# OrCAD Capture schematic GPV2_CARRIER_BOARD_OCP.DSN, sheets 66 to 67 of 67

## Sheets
66 021 PCIE SWITCH (PWR3/VSS3): size C
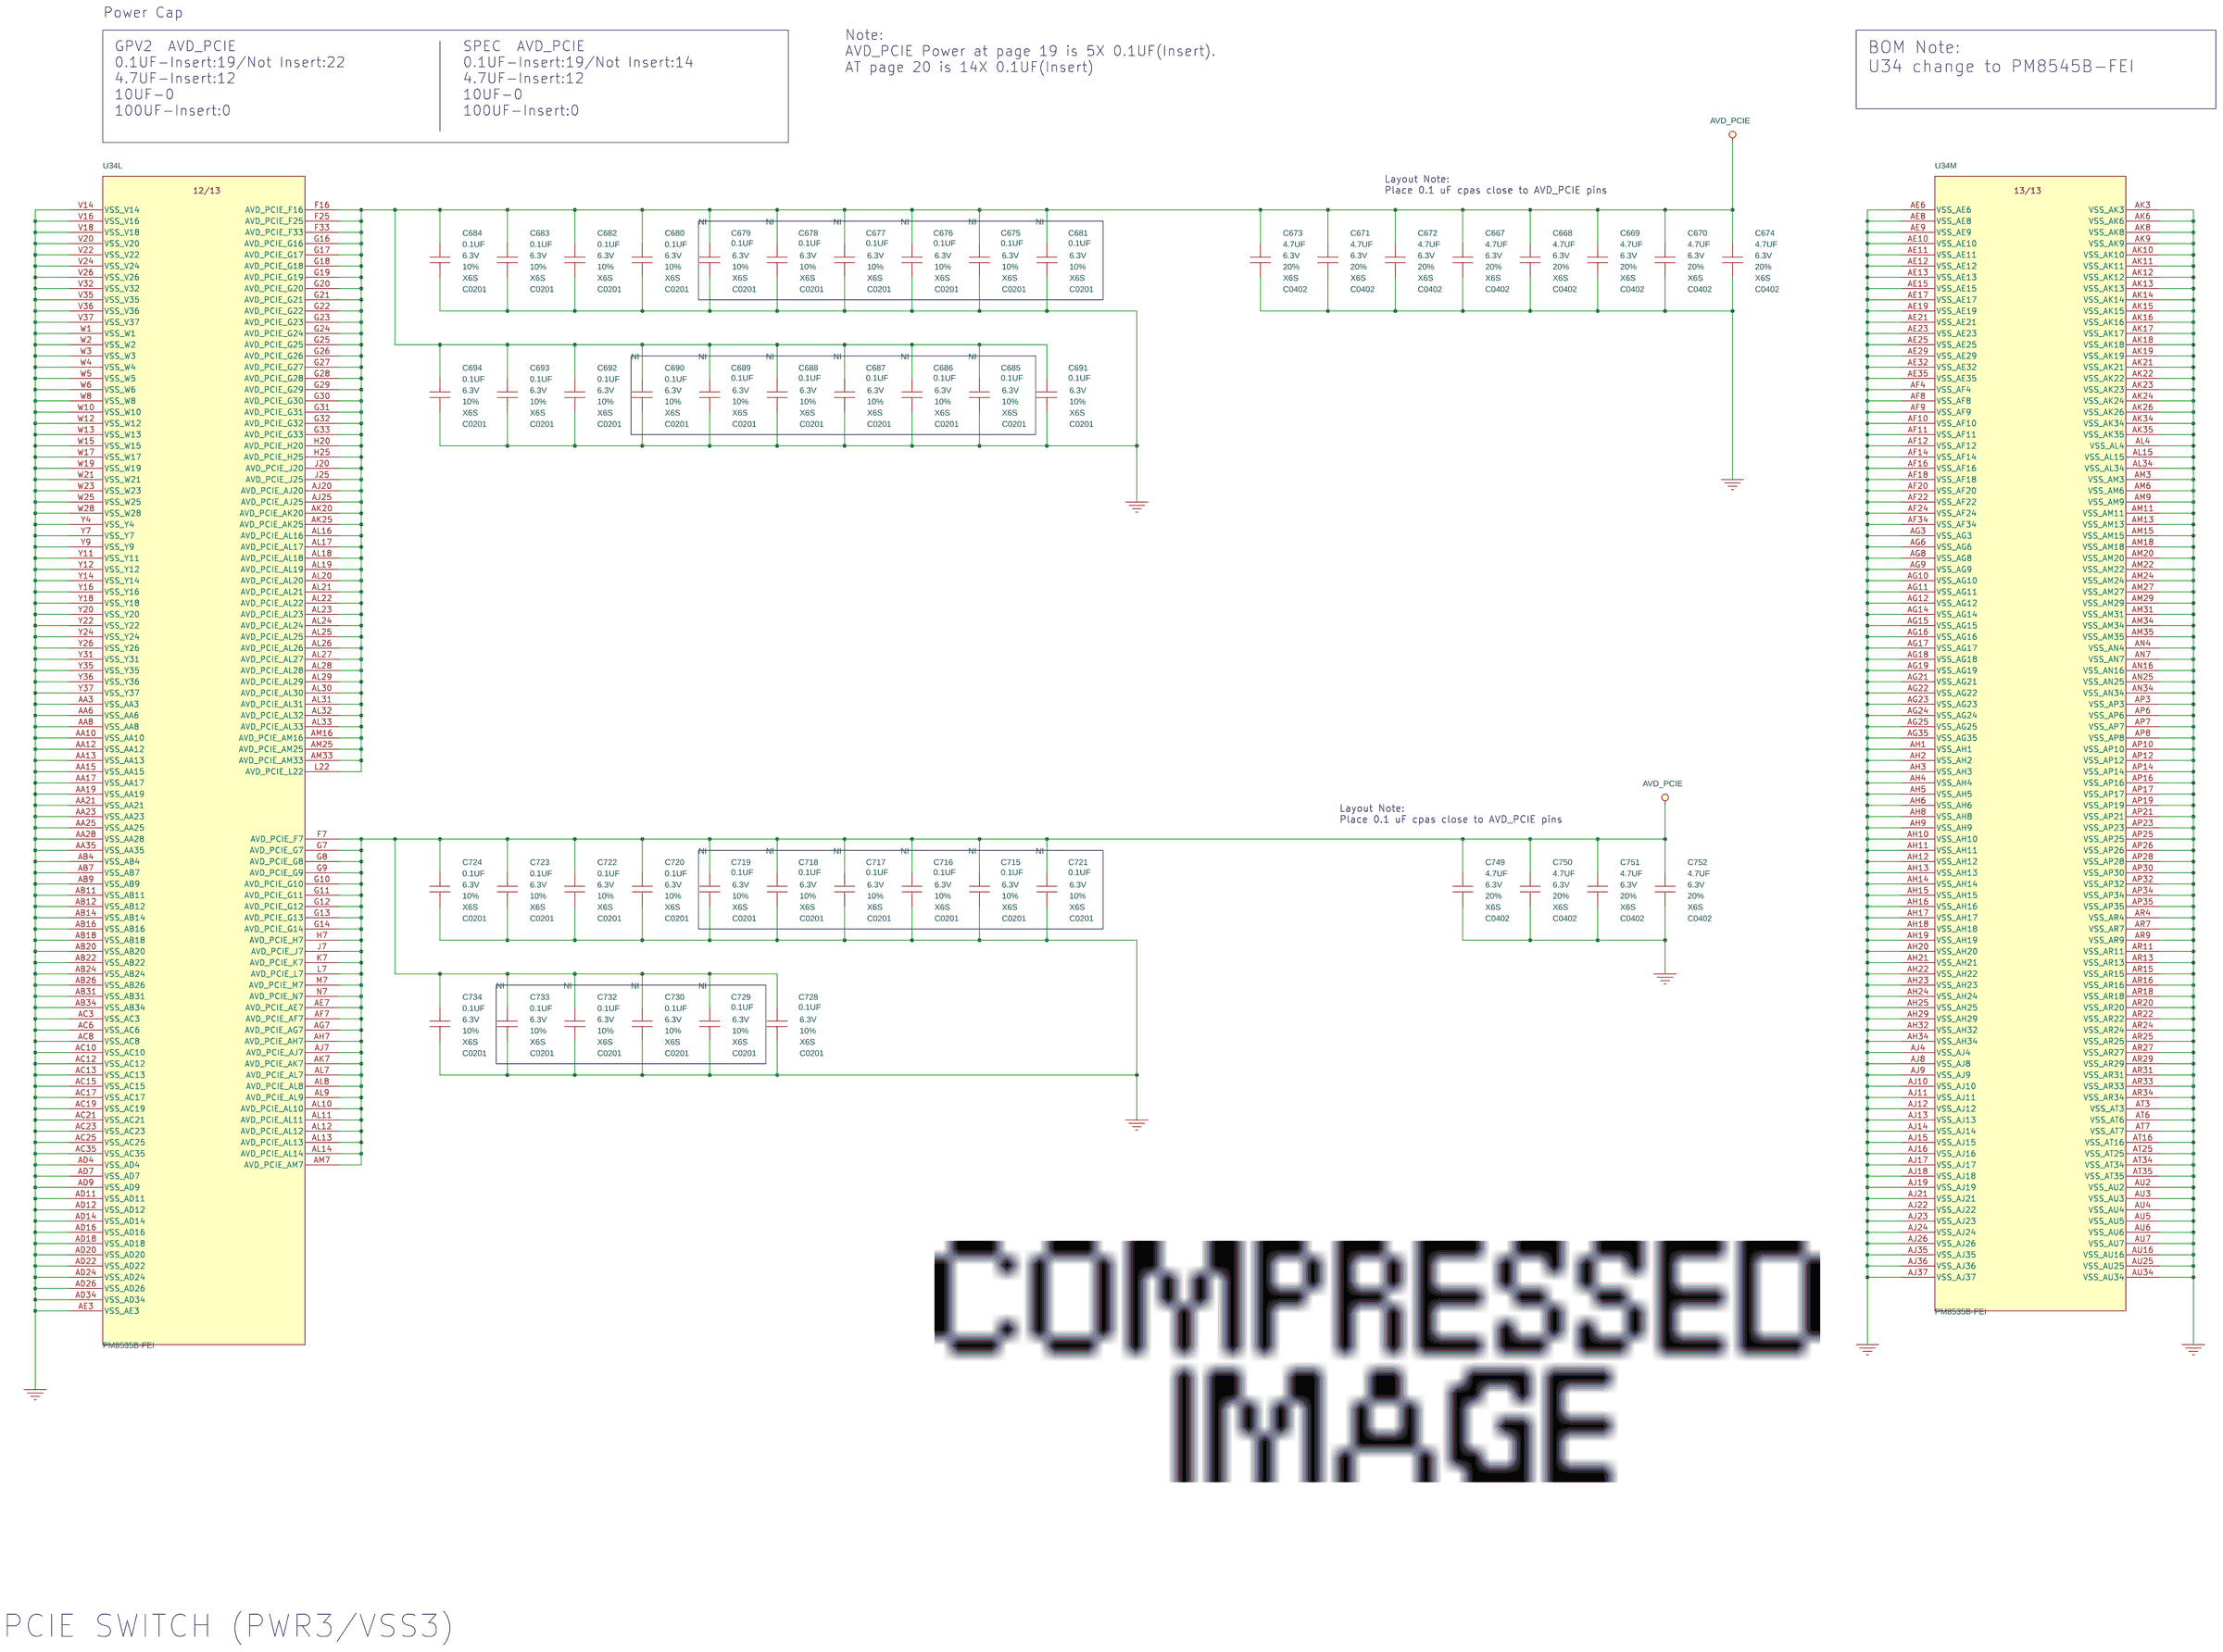
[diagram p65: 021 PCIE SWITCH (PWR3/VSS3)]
67 017 PCIE SWITCH (CLOCKS/RESET): size C
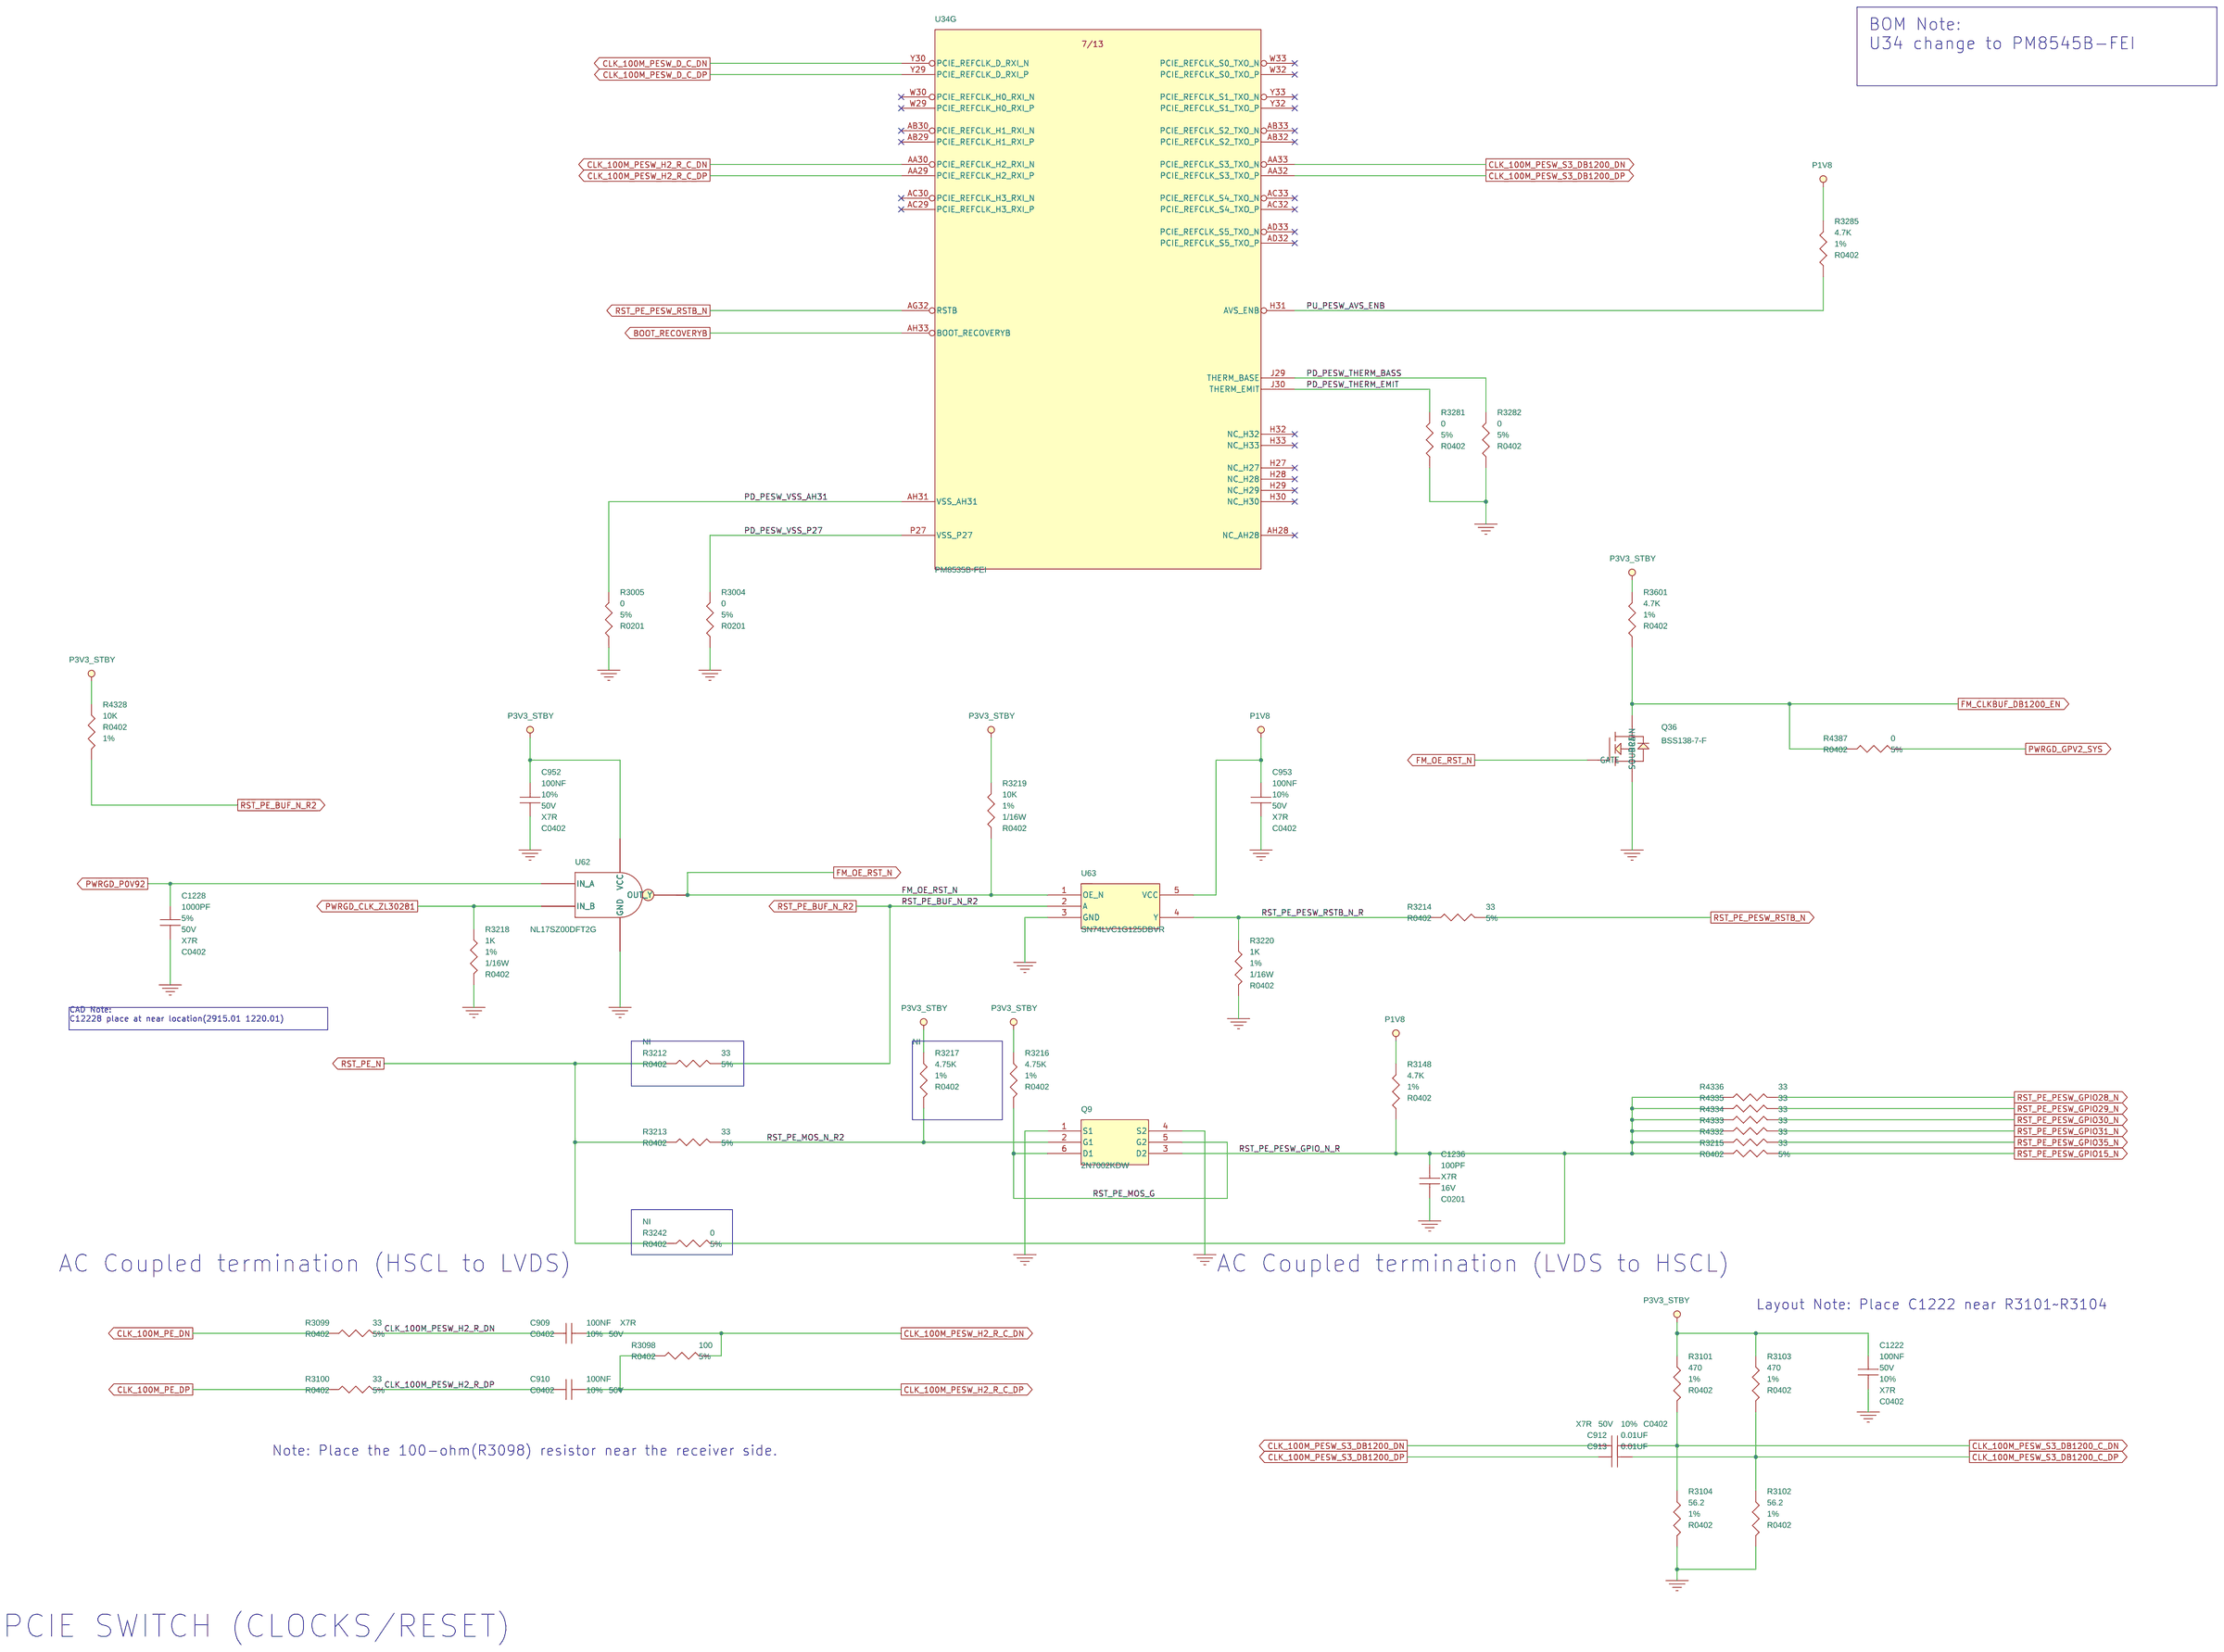
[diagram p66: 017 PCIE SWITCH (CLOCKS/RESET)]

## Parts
sheet 017 PCIE SWITCH (CLOCKS/RESET)
C909  100NF  [C0402]
C910  100NF  [C0402]
C912  0.01UF  [C0402]
C913  0.01UF  [C0402]
C952  100NF  [C0402]
C953  100NF  [C0402]
C1222  100NF  [C0402]
C1228  1000PF  [C0402]
C1236  100PF  [C0201]
Q9  2N7002KDW  [SOT363XD]
Q36  BSS138-7-F  [SOT23_GDSXC]
R3004  0  [R0201]
R3005  0  [R0201]
R3098  100  [R0402]
R3099  33  [R0402]
R3100  33  [R0402]
R3101  470  [R0402]
R3102  56.2  [R0402]
R3103  470  [R0402]
R3104  56.2  [R0402]
R3148  4.7K  [R0402]
R3212  33  [R0402]
R3213  33  [R0402]
R3214  33  [R0402]
R3215  33  [R0402]
R3216  4.75K  [R0402]
R3217  4.75K  [R0402]
R3218  1K  [R0402]
R3219  10K  [R0402]
R3220  1K  [R0402]
R3242  0  [R0402]
R3281  0  [R0402]
R3282  0  [R0402]
R3285  4.7K  [R0402]
R3601  4.7K  [R0402]
R4328  10K  [R0402]
R4332  33  [R0402]
R4333  33  [R0402]
R4334  33  [R0402]
R4335  33  [R0402]
R4336  33  [R0402]
R4387  0  [R0402]
U34  PM8535B-FEI  [BGA1311_1_37-5X37-5]  (sections A,B,C,D,E,F,G,H,I,J,K,L,M)
U62  NL17SZ00DFT2G  [SC70-5XA]
U63  SN74LVC1G125DBVR  [SOT23-5XE]
sheet 021 PCIE SWITCH (PWR3/VSS3)
C667  4.7UF  [C0402]
C668  4.7UF  [C0402]
C669  4.7UF  [C0402]
C670  4.7UF  [C0402]
C671  4.7UF  [C0402]
C672  4.7UF  [C0402]
C673  4.7UF  [C0402]
C674  4.7UF  [C0402]
C675  0.1UF  [C0201]
C676  0.1UF  [C0201]
C677  0.1UF  [C0201]
C678  0.1UF  [C0201]
C679  0.1UF  [C0201]
C680  0.1UF  [C0201]
C681  0.1UF  [C0201]
C682  0.1UF  [C0201]
C683  0.1UF  [C0201]
C684  0.1UF  [C0201]
C685  0.1UF  [C0201]
C686  0.1UF  [C0201]
C687  0.1UF  [C0201]
C688  0.1UF  [C0201]
C689  0.1UF  [C0201]
C690  0.1UF  [C0201]
C691  0.1UF  [C0201]
C692  0.1UF  [C0201]
C693  0.1UF  [C0201]
C694  0.1UF  [C0201]
C715  0.1UF  [C0201]
C716  0.1UF  [C0201]
C717  0.1UF  [C0201]
C718  0.1UF  [C0201]
C719  0.1UF  [C0201]
C720  0.1UF  [C0201]
C721  0.1UF  [C0201]
C722  0.1UF  [C0201]
C723  0.1UF  [C0201]
C724  0.1UF  [C0201]
C728  0.1UF  [C0201]
C729  0.1UF  [C0201]
C730  0.1UF  [C0201]
C732  0.1UF  [C0201]
C733  0.1UF  [C0201]
C734  0.1UF  [C0201]
C749  4.7UF  [C0402]
C750  4.7UF  [C0402]
C751  4.7UF  [C0402]
C752  4.7UF  [C0402]

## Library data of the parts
C909 C910 C952 C953 C1222 = CAP_NP: CAP CHIP 100NF 50V(+-10%,X7R,0402); CLASS: DISCRETE; MATERIAL: X7R; Manuf_PN: CC0402KRX7R9BB104; Manuf_name: YAGEO CORPORATION; Manuftr: YGO; Part_Type: *LF_C0402; TOLERANCE: 10%; VOLTAGE: 50V
C912 C913 = CAP_NP: CAP CHIP 0.01U 50V(+-10%,X7R,0402); CLASS: DISCRETE; MATERIAL: X7R; Manuf_PN: WBM155R71H103K; Manuf_name: MURATA ERIE N.A. INC TAIWAN BRANCH Okayama Murata Mfg.Co.,Ltd.; Manuftr: MUR; Part_Type: *LF_C0402; TOLERANCE: 10%; VOLTAGE: 50V
C1228 = CAP_NP: CAP CHIP 1000P 50V(+-5%.X7R.0402); CLASS: DISCRETE; MATERIAL: X7R; Manuf_PN: C1005X7R102JGT; Manuf_name: ACER PERIPHERALS INC.(Darfon Electronics Corp.); Manuftr: API; Part_Type: *LF_C0402; TOLERANCE: 5%; VOLTAGE: 50V
C1236 = CAP_NP: CAP CHIP 100PF 16V(+-10%,X7R,0201); CLASS: DISCRETE; MATERIAL: X7R; Manuf_PN: GRM033R71C101K; Manuf_name: MURATA ERIE N.A. INC TAIWAN BRANCH Okayama Murata Mfg.Co.,Ltd.Wakura Murata Mfg.; Manuftr: MUR; Part_Type: *LF_C0201; TOLERANCE: 10%; VOLTAGE: 16V
Q9 = MOSFET_DUAL_6P: TRANS MOS 2N7002KDW(60V115MA,0.2W)SOT363; CLASS: IC; MATERIAL: IC; Manuf_name: PAN JIT INTERNATIONAL INC.; Manuftr: PJT; Part_Type: *LF_Semiconductor
Q36 = MOSFET_N_0: TRANS MOSFET BSS138-7-F(50V,0.2A); CLASS: IC; MATERIAL: IC; Manuf_name: DIODES TAIWAN CO.,LTD.; Manuftr: DDS; Part_Type: *LF_Semiconductor
R3004 R3005 = R: RES CHIP 0(1/20W,+-5%,0201); CLASS: DISCRETE; MATERIAL: CHIP; Manuf_PN: RC0201JR-130RL; Manuf_name: YAGEO CORPORATION; Manuftr: YGO; Part_Type: *LF_Resistor; TOLERANCE: 5%; WATTAGE: 1/20W
R3098 = R: RES CHIP 100 1/16W +-5% (0402); CLASS: DISCRETE; MATERIAL: CHIP; Manuf_PN: RR0510S-101-JN; Manuf_name: CYNTEC CO.. LTD.; Manuftr: CYN; Part_Type: *LF_Resistor; TOLERANCE: 5%; WATTAGE: 1/16W
R3099 R3100 = R: RES CHIP 33 1/16W +-5% (0402); BOM: AST2300; CLASS: DISCRETE; MATERIAL: CHIP; Manuf_PN: RR0510S-330-JN; Manuf_name: CYNTEC CO.. LTD.; Manufacturer: CYN; Manuftr: CYN; Part_Type: *LF_Resistor; TOLERANCE: 5%; WATTAGE: 1/16W
R3101 R3103 = R: RES CHIP 470 1/16W +-1%(0402); CLASS: DISCRETE; MATERIAL: CHIP; Manuf_PN: RR0510S-471-FN; Manuf_name: CYNTEC CO.. LTD.; Manuftr: CYN; Part_Type: *LF_Resistor; TOLERANCE: 1%; WATTAGE: 1/16W
R3102 R3104 = R: RES CHIP 56.2 1/16W +-1% (0402); CLASS: DISCRETE; FPLIST: R0402,R0402-0201; MATERIAL: CHIP; Manuf_PN: CR0256R2F002; Manuf_name: "RTECH TECHNOLOGY CO..LTD.(Compostar)"; Manuftr: RHT; Part_Type: Resistor; TOLERANCE: 1%; WATTAGE: 1/16W
R3148 R3285 R3601 = R: RES CHIP 4.7K 1/16W +-1%(0402); CLASS: DISCRETE; MATERIAL: CHIP; Manuf_PN: RTT024701FTH; Manuf_name: RALEC ELECTRONIC CO.; Manuftr: RLC; Part_Type: *LF_Resistor; TOLERANCE: 1%; WATTAGE: 1/16W
R3212 = R: RES CHIP 33 1/16W +-5% (0402); CLASS: DISCRETE; MATERIAL: CHIP; Manuf_PN: RR0510S-330-JN; Manuf_name: CYNTEC CO.. LTD.; Manuftr: CYN; Not_insert: NI; Part_Type: *LF_Resistor; TOLERANCE: 5%; WATTAGE: 1/16W
R3213-R3215 R4332-R4336 = R: RES CHIP 33 1/16W +-5% (0402); CLASS: DISCRETE; MATERIAL: CHIP; Manuf_PN: RR0510S-330-JN; Manuf_name: CYNTEC CO.. LTD.; Manuftr: CYN; Part_Type: *LF_Resistor; TOLERANCE: 5%; WATTAGE: 1/16W
R3216 = R: RES CHIP 4.75K 1/16W +-1%(0402); CLASS: DISCRETE; MATERIAL: CHIP; Manuf_PN: RR0510S-4751-FN; Manuf_name: CYNTEC CO.. LTD.; Manuftr: CYN; Part_Type: *LF_Resistor; TOLERANCE: 1%; WATTAGE: 1/16W
R3217 = R: RES CHIP 4.75K 1/16W +-1%(0402); CLASS: DISCRETE; MATERIAL: CHIP; Manuf_PN: RR0510S-4751-FN; Manuf_name: CYNTEC CO.. LTD.; Manuftr: CYN; Not_insert: NI; Part_Type: *LF_Resistor; TOLERANCE: 1%; WATTAGE: 1/16W
R3218 R3220 = R: RES CHIP 1K 1/16W +-1% (0402); CLASS: DISCRETE; MATERIAL: CHIP; Manuf_PN: RR0510S-102-FN; Manuf_name: CYNTEC CO.. LTD.; Manuftr: CYN; Part_Type: *LF_Resistor; TOLERANCE: 1%; WATTAGE: 1/16W
R3219 = R: RES CHIP 10K 1/16W +-1% (0402); CLASS: DISCRETE; MATERIAL: CHIP; Manuf_PN: RR0510S-103-FN; Manuf_name: CYNTEC CO.. LTD.; Manufacturer: CYN; Manuftr: CYN; Part_Type: *LF_Resistor; TOLERANCE: 1%; WATTAGE: 1/16W
R3242 = R: RESISTOR CHIP 0 1/16W +-5%(0402); BOM: AST2300; CLASS: DISCRETE; MATERIAL: CHIP; Manuf_PN: RR0510X-000-XN; Manuf_name: CYNTEC CO.. LTD.; Manufacturer: CYN; Manuftr: CYN; Not_insert: NI; Part_Type: *LF_Resistor; TOLERANCE: 5%; WATTAGE: 1/16W
R3281 R3282 R4387 = R: RESISTOR CHIP 0 1/16W +-5%(0402); BOM: AST2300; CLASS: DISCRETE; MATERIAL: CHIP; Manuf_PN: RR0510X-000-XN; Manuf_name: CYNTEC CO.. LTD.; Manufacturer: CYN; Manuftr: CYN; Part_Type: *LF_Resistor; TOLERANCE: 5%; WATTAGE: 1/16W
R4328 = R: RES CHIP 10K 1/16W +-1% (0402); CLASS: DISCRETE; FPLIST: R0402,R0402-0201; MATERIAL: CHIP; Manuf_PN: RR0510S-103-FN; Manuf_name: CYNTEC CO.. LTD.; Manufacturer: CYN; Manuftr: CYN; Part_Type: *LF_Resistor; TOLERANCE: 1%; WATTAGE: 1/16W
U34 = PM8535BFEI: IC CTRL(1311P)PM8535B-FEI(FCBGA); CLASS: IC; ESD_CDM: N/A; ESD_HBM: N/A; ESD_MM: N/A; MATERIAL: IC; MSD: NA; Manuf_name: Microsemi Corporation ( Microsemi Taiwan); Manuftr: MST; PIN_LENGTH_LONG_PIN: 0 MILS; PIN_LENGTH_SHORT_PIN: 0 MILS; Part_Type: *LF_Chipset
U62 = NL17SZ00DFT2G: IC OTHER(5P) NL17SZ00DFT2G(SOT-353); CLASS: IC; ESD_CDM: N/A; ESD_HBM: 2000; ESD_MM: 200; MATERIAL: IC; MSD: Level-1; Manuf_name: ON SEMICONDUCTOR; Manuftr: ONS; PIN_LENGTH_LONG_PIN: 0 MILS; PIN_LENGTH_SHORT_PIN: 0 MILS; Part_Type: *LF_Chipset
U63 = SN74LVC1G125DBVR: IC(5P)SN74LVC1G125DBVR(SOT-23); CLASS: IC; MATERIAL: IC; Manuf_name: TEXAS INSTRUMENTS SUPPLY CO.,; Manuftr: TIC; Part_Type: *LF_Chipset
C667-C674 C749-C752 = CAP_NP: CAP CHIP 4.7UF 6.3V(+-20%,X6S,0402); CLASS: DISCRETE; MATERIAL: X6S; Manuf_PN: GRM155C80J475M; Manuf_name: MURATA ERIE N.A. INC TAIWAN BRANCH Okayama Murata Mfg.Co.,; Manuftr: MUR; Part_Type: *LF_C0402; TOLERANCE: 20%; VOLTAGE: 6.3V
C675-C679 C681 C685-C690 C715-C719 C721 C729 C730 C732 C733 = CAP_NP: CAP CHIP 0.1UF 6.3V(10%,X6S,0201,H0.3); CLASS: DISCRETE; MATERIAL: X6S; Manuf_PN: GRM033C80J104K; Manuf_name: MURATA ERIE N.A. INC TAIWAN BRANCH Okayama Murata Mfg.Co.,Ltd.Wakura Murata Mfg.; Manuftr: MUR; Not_insert: NI; Part_Type: *LF_C0201; TOLERANCE: 10%; VOLTAGE: 6.3V
C680 C682-C684 C691-C694 C720 C722-C724 C728 C734 = CAP_NP: CAP CHIP 0.1UF 6.3V(10%,X6S,0201,H0.3); CLASS: DISCRETE; MATERIAL: X6S; Manuf_PN: GRM033C80J104K; Manuf_name: MURATA ERIE N.A. INC TAIWAN BRANCH Okayama Murata Mfg.Co.,Ltd.Wakura Murata Mfg.; Manuftr: MUR; Part_Type: *LF_C0201; TOLERANCE: 10%; VOLTAGE: 6.3V

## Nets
GND: C667.2 C668.2 C669.2 C670.2 C671.2 C672.2 C673.2 C674.2 C675.2 C676.2 C677.2 C678.2 C679.2 C680.2 C681.2 C682.2 C683.2 C684.2 C685.2 C686.2 C687.2 C688.2 C689.2 C690.2 C691.2 C692.2 C693.2 C694.2 C715.2 C716.2 C717.2 C718.2 C719.2 C720.2 C721.2 C722.2 C723.2 C724.2 C728.2 C729.2 C730.2 C732.2 C733.2 C734.2 C749.2 C750.2 C751.2 C752.2 C952.1 C953.1 C1222.2 C1228.2 C1236.2 Q9.1(S1) Q9.4(S2) Q36.S(SOURCE) R3004.1 R3005.1 R3102.2 R3104.2 R3218.2 R3220.2 R3281.1 R3282.1 U34.AA3(VSS) U34.AA6(VSS) U34.AA8(VSS) U34.AA10(VSS) U34.AA12(VSS) U34.AA13(VSS) U34.AA15(VSS) U34.AA17(VSS) U34.AA19(VSS) U34.AA21(VSS) U34.AA23(VSS) U34.AA25(VSS) U34.AA28(VSS) U34.AA35(VSS) U34.AB4(VSS) U34.AB7(VSS) U34.AB9(VSS) U34.AB11(VSS) U34.AB12(VSS) U34.AB14(VSS) U34.AB16(VSS) U34.AB18(VSS) U34.AB20(VSS) U34.AB22(VSS) U34.AB24(VSS) U34.AB26(VSS) U34.AB31(VSS) U34.AB34(VSS) U34.AC3(VSS) U34.AC6(VSS) U34.AC8(VSS) U34.AC10(VSS) U34.AC12(VSS) U34.AC13(VSS) U34.AC15(VSS) U34.AC17(VSS) U34.AC19(VSS) U34.AC21(VSS) U34.AC23(VSS) U34.AC25(VSS) U34.AC35(VSS) U34.AD4(VSS) U34.AD7(VSS) U34.AD9(VSS) U34.AD11(VSS) U34.AD12(VSS) U34.AD14(VSS) U34.AD16(VSS) U34.AD18(VSS) U34.AD20(VSS) U34.AD22(VSS) U34.AD24(VSS) U34.AD26(VSS) U34.AD34(VSS) U34.AE3(VSS) U34.AE6(VSS) U34.AE8(VSS) U34.AE9(VSS) U34.AE10(VSS) U34.AE11(VSS) U34.AE12(VSS) U34.AE13(VSS) U34.AE15(VSS) U34.AE17(VSS) U34.AE19(VSS) U34.AE21(VSS) U34.AE23(VSS) U34.AE25(VSS) U34.AE29(VSS) U34.AE32(VSS) U34.AE35(VSS) U34.AF4(VSS) U34.AF8(VSS) U34.AF9(VSS) U34.AF10(VSS) U34.AF11(VSS) U34.AF12(VSS) U34.AF14(VSS) U34.AF16(VSS) U34.AF18(VSS) U34.AF20(VSS) U34.AF22(VSS) U34.AF24(VSS) U34.AF34(VSS) U34.AG3(VSS) U34.AG6(VSS) U34.AG8(VSS) U34.AG9(VSS) U34.AG10(VSS) U34.AG11(VSS) U34.AG12(VSS) U34.AG14(VSS) U34.AG15(VSS) U34.AG16(VSS) U34.AG17(VSS) U34.AG18(VSS) U34.AG19(VSS) U34.AG21(VSS) U34.AG22(VSS) U34.AG23(VSS) U34.AG24(VSS) U34.AG25(VSS) U34.AG35(VSS) U34.AH1(VSS) U34.AH2(VSS) U34.AH3(VSS) U34.AH4(VSS) U34.AH5(VSS) U34.AH6(VSS) U34.AH8(VSS) U34.AH9(VSS) U34.AH10(VSS) U34.AH11(VSS) U34.AH12(VSS) U34.AH13(VSS) U34.AH14(VSS) U34.AH15(VSS) U34.AH16(VSS) U34.AH17(VSS) U34.AH18(VSS) U34.AH19(VSS) U34.AH20(VSS) U34.AH21(VSS) U34.AH22(VSS) U34.AH23(VSS) U34.AH24(VSS) U34.AH25(VSS) U34.AH29(VSS) U34.AH32(VSS) U34.AH34(VSS) U34.AJ4(VSS) U34.AJ8(VSS) U34.AJ9(VSS) U34.AJ10(VSS) U34.AJ11(VSS) U34.AJ12(VSS) U34.AJ13(VSS) U34.AJ14(VSS) U34.AJ15(VSS) U34.AJ16(VSS) U34.AJ17(VSS) U34.AJ18(VSS) U34.AJ19(VSS) U34.AJ21(VSS) U34.AJ22(VSS) U34.AJ23(VSS) U34.AJ24(VSS) U34.AJ26(VSS) U34.AJ35(VSS) U34.AJ36(VSS) U34.AJ37(VSS) U34.AK3(VSS) U34.AK6(VSS) U34.AK8(VSS) U34.AK9(VSS) U34.AK10(VSS) U34.AK11(VSS) U34.AK12(VSS) U34.AK13(VSS) U34.AK14(VSS) U34.AK15(VSS) U34.AK16(VSS) U34.AK17(VSS) U34.AK18(VSS) U34.AK19(VSS) U34.AK21(VSS) U34.AK22(VSS) U34.AK23(VSS) U34.AK24(VSS) U34.AK26(VSS) U34.AK34(VSS) U34.AK35(VSS) U34.AL4(VSS) U34.AL15(VSS) U34.AL34(VSS) U34.AM3(VSS) U34.AM6(VSS) U34.AM9(VSS) U34.AM11(VSS) U34.AM13(VSS) U34.AM15(VSS) U34.AM18(VSS) U34.AM20(VSS) U34.AM22(VSS) U34.AM24(VSS) U34.AM27(VSS) U34.AM29(VSS) U34.AM31(VSS) U34.AM34(VSS) U34.AM35(VSS) U34.AN4(VSS) U34.AN7(VSS) U34.AN16(VSS) U34.AN25(VSS) U34.AN34(VSS) U34.AP3(VSS) U34.AP6(VSS) U34.AP7(VSS) U34.AP8(VSS) U34.AP10(VSS) U34.AP12(VSS) U34.AP14(VSS) U34.AP16(VSS) U34.AP17(VSS) U34.AP19(VSS) U34.AP21(VSS) U34.AP23(VSS) U34.AP25(VSS) U34.AP26(VSS) U34.AP28(VSS) U34.AP30(VSS) U34.AP32(VSS) U34.AP34(VSS) U34.AP35(VSS) U34.AR4(VSS) U34.AR7(VSS) U34.AR9(VSS) U34.AR11(VSS) U34.AR13(VSS) U34.AR15(VSS) U34.AR16(VSS) U34.AR18(VSS) U34.AR20(VSS) U34.AR22(VSS) U34.AR24(VSS) U34.AR25(VSS) U34.AR27(VSS) U34.AR29(VSS) U34.AR31(VSS) U34.AR33(VSS) U34.AR34(VSS) U34.AT3(VSS) U34.AT6(VSS) U34.AT7(VSS) U34.AT16(VSS) U34.AT25(VSS) U34.AT34(VSS) U34.AT35(VSS) U34.AU2(VSS) U34.AU3(VSS) U34.AU4(VSS) U34.AU5(VSS) U34.AU6(VSS) U34.AU7(VSS) U34.AU16(VSS) U34.AU25(VSS) U34.AU34(VSS) U34.V14(VSS) U34.V16(VSS) U34.V18(VSS) U34.V20(VSS) U34.V22(VSS) U34.V24(VSS) U34.V26(VSS) U34.V32(VSS) U34.V35(VSS) U34.V36(VSS) U34.V37(VSS) U34.W1(VSS) U34.W2(VSS) U34.W3(VSS) U34.W4(VSS) U34.W5(VSS) U34.W6(VSS) U34.W8(VSS) U34.W10(VSS) U34.W12(VSS) U34.W13(VSS) U34.W15(VSS) U34.W17(VSS) U34.W19(VSS) U34.W21(VSS) U34.W23(VSS) U34.W25(VSS) U34.W28(VSS) U34.Y4(VSS) U34.Y7(VSS) U34.Y9(VSS) U34.Y11(VSS) U34.Y12(VSS) U34.Y14(VSS) U34.Y16(VSS) U34.Y18(VSS) U34.Y20(VSS) U34.Y22(VSS) U34.Y24(VSS) U34.Y26(VSS) U34.Y31(VSS) U34.Y35(VSS) U34.Y36(VSS) U34.Y37(VSS) U62.3(GND) U63.3(GND) ; also on sheet 12 13 17 18 19 20 21 22 23 24 25 26 27 28 29 30 31 32 33 34 35 36 37 38 39 40 41 42 43 44 45 46 47 48 49 50 52 53 54 55 56 57 58 61 62 63 64 65
P1V8: C953.2 R3148.2 R3285.2 U63.5(VCC) ; also on sheet 17 18 19 22 23 24 25 26 27 28 29 30 31 32 33 34 35 36 37 44 49 50 53 58 62 65
P3V3_STBY: C952.2 C1222.1 R3101.1 R3103.1 R3216.1 R3217.1 R3219.1 R3601.2 R4328.1 U62.5(VCC) ; also on sheet 12 17 18 19 20 22 23 24 25 26 27 28 29 30 31 32 33 34 35 36 37 38 39 40 41 42 43 44 45 46 47 48 49 50 52 53 54 55 56 57 58 61
AVD_PCIE: C667.1 C668.1 C669.1 C670.1 C671.1 C672.1 C673.1 C674.1 C675.1 C676.1 C677.1 C678.1 C679.1 C680.1 C681.1 C682.1 C683.1 C684.1 C685.1 C686.1 C687.1 C688.1 C689.1 C690.1 C691.1 C692.1 C693.1 C694.1 C715.1 C716.1 C717.1 C718.1 C719.1 C720.1 C721.1 C722.1 C723.1 C724.1 C728.1 C729.1 C730.1 C732.1 C733.1 C734.1 C749.1 C750.1 C751.1 C752.1 U34.AE7(AVD_PCIE) U34.AF7(AVD_PCIE) U34.AG7(AVD_PCIE) U34.AH7(AVD_PCIE) U34.AJ7(AVD_PCIE) U34.AJ20(AVD_PCIE) U34.AJ25(AVD_PCIE) U34.AK7(AVD_PCIE) U34.AK20(AVD_PCIE) U34.AK25(AVD_PCIE) U34.AL7(AVD_PCIE) U34.AL8(AVD_PCIE) U34.AL9(AVD_PCIE) U34.AL10(AVD_PCIE) U34.AL11(AVD_PCIE) U34.AL12(AVD_PCIE) U34.AL13(AVD_PCIE) U34.AL14(AVD_PCIE) U34.AL16(AVD_PCIE) U34.AL17(AVD_PCIE) U34.AL18(AVD_PCIE) U34.AL19(AVD_PCIE) U34.AL20(AVD_PCIE) U34.AL21(AVD_PCIE) U34.AL22(AVD_PCIE) U34.AL23(AVD_PCIE) U34.AL24(AVD_PCIE) U34.AL25(AVD_PCIE) U34.AL26(AVD_PCIE) U34.AL27(AVD_PCIE) U34.AL28(AVD_PCIE) U34.AL29(AVD_PCIE) U34.AL30(AVD_PCIE) U34.AL31(AVD_PCIE) U34.AL32(AVD_PCIE) U34.AL33(AVD_PCIE) U34.AM7(AVD_PCIE) U34.AM16(AVD_PCIE) U34.AM25(AVD_PCIE) U34.AM33(AVD_PCIE) U34.F7(AVD_PCIE) U34.F16(AVD_PCIE) U34.F25(AVD_PCIE) U34.F33(AVD_PCIE) U34.G7(AVD_PCIE) U34.G8(AVD_PCIE) U34.G9(AVD_PCIE) U34.G10(AVD_PCIE) U34.G11(AVD_PCIE) U34.G12(AVD_PCIE) U34.G13(AVD_PCIE) U34.G14(AVD_PCIE) U34.G16(AVD_PCIE) U34.G17(AVD_PCIE) U34.G18(AVD_PCIE) U34.G19(AVD_PCIE) U34.G20(AVD_PCIE) U34.G21(AVD_PCIE) U34.G22(AVD_PCIE) U34.G23(AVD_PCIE) U34.G24(AVD_PCIE) U34.G25(AVD_PCIE) U34.G26(AVD_PCIE) U34.G27(AVD_PCIE) U34.G28(AVD_PCIE) U34.G29(AVD_PCIE) U34.G30(AVD_PCIE) U34.G31(AVD_PCIE) U34.G32(AVD_PCIE) U34.G33(AVD_PCIE) U34.H7(AVD_PCIE) U34.H20(AVD_PCIE) U34.H25(AVD_PCIE) U34.J7(AVD_PCIE) U34.J20(AVD_PCIE) U34.J25(AVD_PCIE) U34.K7(AVD_PCIE) U34.L7(AVD_PCIE) U34.L22(AVD_PCIE) U34.M7(AVD_PCIE) U34.N7(AVD_PCIE) ; also on sheet 64
BOOT_RECOVERYB: U34.AH33(BOOT_RECOVERYB) ; also on sheet 17
CLK_100M_PE_DN: R3099.1 ; also on sheet 12
CLK_100M_PE_DP: R3100.1 ; also on sheet 12
CLK_100M_PESW_D_C_DN: U34.Y30(PCIE_REFCLK_D_RXI_N) ; also on sheet 19
CLK_100M_PESW_D_C_DP: U34.Y29(PCIE_REFCLK_D_RXI_P) ; also on sheet 19
CLK_100M_PESW_H2_R_C_DN: C909.2 R3098.2 U34.AA30(PCIE_REFCLK_H2_RXI_N)
CLK_100M_PESW_H2_R_C_DP: C910.2 R3098.1 U34.AA29(PCIE_REFCLK_H2_RXI_P)
CLK_100M_PESW_H2_R_DN: C909.1 R3099.2
CLK_100M_PESW_H2_R_DP: C910.1 R3100.2
CLK_100M_PESW_S3_DB1200_C_DN: C912.2 R3101.2 R3104.1 ; also on sheet 20
CLK_100M_PESW_S3_DB1200_C_DP: C913.2 R3102.1 R3103.2 ; also on sheet 20
CLK_100M_PESW_S3_DB1200_DN: C912.1 U34.AA33(PCIE_REFCLK_S3_TXO_N)
CLK_100M_PESW_S3_DB1200_DP: C913.1 U34.AA32(PCIE_REFCLK_S3_TXO_P)
FM_CLKBUF_DB1200_EN: Q36.D(DRAIN) R3601.1 R4387.1 ; also on sheet 20
FM_OE_RST_N: Q36.G(GATE) R3219.2 U62.4(OUT_Y) U63.1(OE_N)
PD_PESW_THERM_BASS: R3282.2 U34.J29(THERM_BASE)
PD_PESW_THERM_EMIT: R3281.2 U34.J30(THERM_EMIT)
PD_PESW_VSS_AH31: R3005.2 U34.AH31(VSS)
PD_PESW_VSS_P27: R3004.2 U34.P27(VSS)
PU_PESW_AVS_ENB: R3285.1 U34.H31(AVS_ENB)
PWRGD_CLK_ZL30281: R3218.1 U62.2(IN_B) ; also on sheet 19
PWRGD_GPV2_SYS: R4387.2 ; also on sheet 47
PWRGD_P0V92: C1228.1 U62.1(IN_A) ; also on sheet 57
RST_PE_BUF_N_R2: R3212.2 R4328.2 U63.2(A)
RST_PE_MOS_G: Q9.5(G2) Q9.6(D1) R3216.2
RST_PE_MOS_N_R2: Q9.2(G1) R3213.2 R3217.2
RST_PE_N: R3212.1 R3213.1 R3242.1 ; also on sheet 12 46
RST_PE_PESW_GPIO15_N: R3215.2 ; also on sheet 17
RST_PE_PESW_GPIO28_N: R4336.2 ; also on sheet 17
RST_PE_PESW_GPIO29_N: R4335.2 ; also on sheet 17
RST_PE_PESW_GPIO30_N: R4334.2 ; also on sheet 17
RST_PE_PESW_GPIO31_N: R4333.2 ; also on sheet 17
RST_PE_PESW_GPIO35_N: R4332.2 ; also on sheet 17
RST_PE_PESW_GPIO_N_R: C1236.1 Q9.3(D2) R3148.1 R3215.1 R3242.2 R4332.1 R4333.1 R4334.1 R4335.1 R4336.1
RST_PE_PESW_RSTB_N: R3214.2 U34.AG32(RSTB)
RST_PE_PESW_RSTB_N_R: R3214.1 R3220.1 U63.4(Y)

Not connected (* = marked no-connect by the designer): U34 AB29(PCIE_REFCLK_H1_RXI_P)* AB30(PCIE_REFCLK_H1_RXI_N)* AB32(PCIE_REFCLK_S2_TXO_P)* AB33(PCIE_REFCLK_S2_TXO_N)* AC29(PCIE_REFCLK_H3_RXI_P)* AC30(PCIE_REFCLK_H3_RXI_N)* AC32(PCIE_REFCLK_S4_TXO_P)* AC33(PCIE_REFCLK_S4_TXO_N)* AD32(PCIE_REFCLK_S5_TXO_P)* AD33(PCIE_REFCLK_S5_TXO_N)* AH28(NC)* H27(NC)* H28(NC)* H29(NC)* H30(NC)* H32(NC)* H33(NC)* W29(PCIE_REFCLK_H0_RXI_P)* W30(PCIE_REFCLK_H0_RXI_N)* W32(PCIE_REFCLK_S0_TXO_P)* W33(PCIE_REFCLK_S0_TXO_N)* Y32(PCIE_REFCLK_S1_TXO_P)* Y33(PCIE_REFCLK_S1_TXO_N)*

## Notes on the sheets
sheet 66
- Power Cap
- Note:
  AVD_PCIE Power at page 19 is 5X 0.1UF(Insert).
  AT page 20 is 14X 0.1UF(Insert)
- 0.1UF-Insert:19/Not Insert:22
  4.7UF-Insert:12
  10UF-0
  100UF-Insert:0
- GPV2  AVD_PCIE
- 0.1UF-Insert:19/Not Insert:14
  4.7UF-Insert:12
  10UF-0
  100UF-Insert:0
- SPEC  AVD_PCIE
- BOM Note:
  U34 change to PM8545B-FEI
- Layout Note:
  Place 0.1 uF cpas close to AVD_PCIE pins
- Layout Note:
  Place 0.1 uF cpas close to AVD_PCIE pins
- PCIE SWITCH (PWR3/VSS3)
sheet 67
- BOM Note:
  U34 change to PM8545B-FEI
- CAD Note:
  C12228 place at near location(2915.01 1220.01)
- AC Coupled termination (HSCL to LVDS)
- AC Coupled termination (LVDS to HSCL)
- Layout Note: Place C1222 near R3101~R3104
- Note: Place the 100-ohm(R3098) resistor near the receiver side.
- PCIE SWITCH (CLOCKS/RESET)
